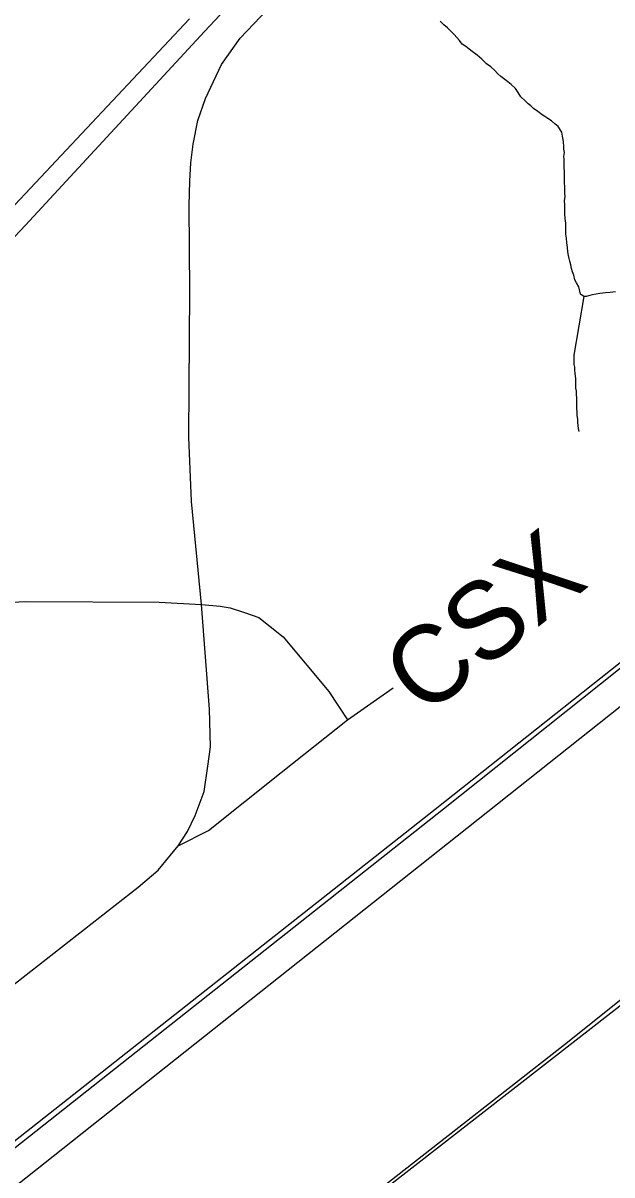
# Model space of a CAD drawing. Extents: x 0 to 44.3, y 0 to 22.
# Drawn here: x 6.767 to 7.197, y 19.51 to 20.352 of the extents above; entities that cross this region are included whole.
import ezdxf

# ---------------------------------------------------------------- set-up
doc = ezdxf.new("R2010")
doc.units = 0
for name, color, linetype in [('GM_X_City_Street', 7, 'Continuous'), ('GM_X_County_Road', 7, 'Continuous'), ('GM_X_Minor_River', 7, 'Continuous'), ('GM_X_Rail_Line', 7, 'Continuous'), ('GM_X_Rail_Line_Text', 7, 'Continuous'), ('GM_X_State_Route', 7, 'Continuous'), ('GM_X_US_Route', 7, 'Continuous')]:
    doc.layers.add(name, color=color, linetype=linetype)

msp = doc.modelspace()

# ---------------------------------------------------------------- linework, layer by layer
at = {"layer": 'GM_X_City_Street'}
for points in [[(6.64281, 19.9233), (6.76883, 19.92908), (6.86623, 19.92839), (6.89711, 19.92684), (6.91075, 19.92546), (6.91817, 19.92425), (6.92869, 19.92097), (6.93904, 19.91717), (6.9475, 19.91078), (6.9568, 19.90304), (6.99031, 19.86311), (7.00385, 19.84242)], [(6.95548, 19.80388), (7.00385, 19.84242), (7.0373, 19.86588)], [(6.88016, 19.75043), (6.90226, 19.76148), (6.95548, 19.80388)]]:
    msp.add_lwpolyline(points, dxfattribs=at)
at = {"layer": 'GM_X_County_Road'}
msp.add_lwpolyline([(6.72151, 19.61927), (6.85093, 19.72012), (6.86555, 19.7326), (6.88016, 19.75043), (6.88694, 19.76077), (6.89264, 19.77254), (6.89905, 19.79001), (6.9019, 19.80855), (6.90369, 19.82281), (6.90297, 19.85027), (6.89711, 19.92684), (6.88991, 20.00222), (6.8878, 20.04905), (6.88822, 20.08574), (6.88864, 20.15577), (6.88822, 20.21862), (6.88871, 20.2364), (6.88936, 20.24984), (6.89109, 20.26349), (6.89442, 20.28083), (6.90002, 20.29676), (6.91177, 20.3216), (6.92537, 20.341), (7.00489, 20.42442)], dxfattribs=at)
at = {"layer": 'GM_X_Minor_River'}
for points in [[(7.16303, 20.22505), (7.16296, 20.22771), (7.16291, 20.22962), (7.16285, 20.2319), (7.16277, 20.23533), (7.16271, 20.23761), (7.16265, 20.23989), (7.1626, 20.24179), (7.16255, 20.2437), (7.16249, 20.24598), (7.16243, 20.24827), (7.16238, 20.25055), (7.16233, 20.25245), (7.16228, 20.25436), (7.16258, 20.25741), (7.16214, 20.25968), (7.16209, 20.26159), (7.16201, 20.26501), (7.16158, 20.26691), (7.16114, 20.26918), (7.16068, 20.27221), (7.15791, 20.27633), (7.15557, 20.27818), (7.15323, 20.2804), (7.15052, 20.28224), (7.14819, 20.2837), (7.14626, 20.2848), (7.14315, 20.28738), (7.14004, 20.28959), (7.13809, 20.29144), (7.13615, 20.29292), (7.13381, 20.29514), (7.13068, 20.29811), (7.1287, 20.30111), (7.12672, 20.3041), (7.1236, 20.30707), (7.12009, 20.31003), (7.11815, 20.3115), (7.11621, 20.31297), (7.11388, 20.31482), (7.11152, 20.31743), (7.10879, 20.32002), (7.10568, 20.32223), (7.10217, 20.32557), (7.09867, 20.32852), (7.09517, 20.3311), (7.09284, 20.33295), (7.09051, 20.33479), (7.08779, 20.33663), (7.08582, 20.33924), (7.08386, 20.34148), (7.0819, 20.34371), (7.07955, 20.34594), (7.0772, 20.34854), (7.07448, 20.35076), (7.07175, 20.35336)], [(7.19985, 20.15553), (7.19606, 20.15505), (7.19264, 20.15459), (7.19074, 20.15454), (7.18846, 20.1541), (7.18581, 20.15365), (7.18315, 20.1532), (7.18126, 20.15277), (7.17861, 20.15194), (7.17671, 20.1519), (7.17438, 20.15374), (7.1731, 20.15904), (7.1715, 20.16205), (7.1703, 20.1643), (7.16945, 20.16771), (7.16863, 20.16997), (7.1678, 20.17261), (7.16735, 20.17527), (7.16652, 20.17791), (7.16609, 20.17981), (7.16565, 20.18208), (7.1652, 20.18474), (7.16475, 20.18777), (7.16428, 20.19118), (7.16419, 20.19461), (7.16373, 20.19764), (7.16362, 20.20183), (7.16353, 20.20564), (7.16306, 20.20905), (7.16297, 20.21248), (7.16288, 20.21591), (7.1628, 20.21895), (7.16273, 20.22199), (7.16303, 20.22505)], [(7.17671, 20.1519), (7.16943, 20.10906), (7.16951, 20.10601), (7.16955, 20.10411), (7.1696, 20.10221), (7.17003, 20.10031), (7.17009, 20.09803), (7.17015, 20.09575), (7.17063, 20.09195), (7.1707, 20.08929), (7.17075, 20.087), (7.1708, 20.0851), (7.17124, 20.08282), (7.17131, 20.08016), (7.17137, 20.07788), (7.17144, 20.07521), (7.17151, 20.07217), (7.17156, 20.07027), (7.17164, 20.06722), (7.1717, 20.06494), (7.17215, 20.06228), (7.17221, 20.06), (7.17271, 20.05544), (7.17325, 20.05327)]]:
    msp.add_lwpolyline(points, dxfattribs=at)
at = {"layer": 'GM_X_Rail_Line'}
for points in [[(5.56513, 18.76798), (5.6149, 18.77572), (5.66544, 18.78761), (5.729, 18.80531), (5.80514, 18.8321), (5.88221, 18.86669), (5.94993, 18.90488), (5.99654, 18.93252), (6.04939, 18.97052), (6.27832, 19.15151), (6.65109, 19.44865), (7.06803, 19.77704), (7.50687, 20.12494), (7.88155, 20.41814), (8.1527, 20.63414), (8.48759, 20.9)], [(5.5655, 18.7657), (5.61535, 18.77344), (5.66602, 18.78537), (5.7297, 18.8031), (5.806, 18.82994), (5.88327, 18.86462), (5.95114, 18.9029), (6.00093, 18.93159), (6.05433, 18.96936), (6.28021, 19.14816), (6.65573, 19.44687), (7.07421, 19.77735), (7.50832, 20.12312), (7.883, 20.41633), (8.15415, 20.63233), (8.49132, 20.9)], [(5.58839, 18.58756), (5.6031, 18.59446), (5.61773, 18.6024), (5.63079, 18.61006), (5.64402, 18.61868), (5.66457, 18.63303), (5.68102, 18.64553), (6.02464, 18.9178), (6.11534, 18.98987), (6.2212, 19.07364), (6.33867, 19.16676), (6.41276, 19.22554), (6.50701, 19.3002), (6.62061, 19.39017), (6.72711, 19.47491), (7.08412, 19.75765), (7.37444, 19.988), (7.70589, 20.25099), (7.98011, 20.4681), (7.9935, 20.47872), (8.00553, 20.48761), (8.02059, 20.4989), (8.0359, 20.5097)], [(8.9, 20.33755), (8.84921, 20.30037), (8.7465, 20.21938), (8.70662, 20.19157), (8.57462, 20.14396), (8.33119, 20.05636), (7.27582, 19.67296), (7.22627, 19.6512), (6.61974, 19.17899), (6.34339, 18.94899), (5.9721, 18.70685), (5.93802, 18.69104), (5.84794, 18.63141), (5.77124, 18.56813), (5.73351, 18.54623), (5.47425, 18.44649)]]:
    msp.add_lwpolyline(points, dxfattribs=at)
at = {"layer": 'GM_X_State_Route'}
for points in [[(6.53245, 19.95458), (6.53447, 19.95677), (6.57818, 20.00261), (6.66815, 20.09791), (6.76851, 20.20417), (6.89923, 20.34577), (7.04028, 20.49617)], [(6.0082, 19.49122), (6.04237, 19.50968), (6.07314, 19.52744), (6.1076, 19.54936), (6.13561, 19.56883), (6.15925, 19.58754), (6.17871, 19.60384), (6.19898, 19.62137), (6.22448, 19.64521), (6.29176, 19.71612), (6.34114, 19.76802), (6.39904, 19.83108), (6.53483, 19.97837), (6.57693, 20.02276), (6.6573, 20.10792), (6.757, 20.21518), (6.88842, 20.35507)]]:
    msp.add_lwpolyline(points, dxfattribs=at)
at = {"layer": 'GM_X_US_Route'}
for points in [[(7.17489, 19.6148), (7.20377, 19.63791), (7.22283, 19.64911), (7.23643, 19.65591), (7.25066, 19.66368), (7.52381, 19.764), (7.53967, 19.76982)], [(6.71027, 19.24607), (6.76943, 19.29409), (6.84387, 19.35429), (6.9471, 19.43552), (7.03383, 19.50445), (7.16474, 19.60667), (7.17489, 19.6148)]]:
    msp.add_lwpolyline(points, dxfattribs=at)

# ---------------------------------------------------------------- texts
at = {"layer": 'GM_X_Rail_Line_Text'}
msp.add_text('CSX', height=0.056629, rotation=38.61909, dxfattribs=at).set_placement((7.05995, 19.84365))

doc.saveas('drawing.dxf')
